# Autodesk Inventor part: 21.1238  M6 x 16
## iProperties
Created: 2006-02
Part Number: 21.1238  M6 x 16
Material: Steel, Mild
Description: Cylinder Head Cap Screw
Document SubType Name: Modeling
Standard: DIN 7984
Designer: Andy Moles
Standards Organization: DIN
Language: en-US
Size Designation: M6 x 16
Categories: <MemberInstance><Categories><Category DisplayName="Fasteners" InternalName="e4da775c-781d-43d5-af7c-5136215cf5a6" Mnemonic="FSTN"><Category DisplayName="Bolts"
Density: 7.86 g/cm^3
Mass: 5.59687 g
Surface Area: 6.14162 cm^2
Volume: 0.71207 cm^3
Author: Andy Moles
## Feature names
1. Body [Revolution]
2. Slot [Extrusion]
3. Fillet1
4. Chamfer1
